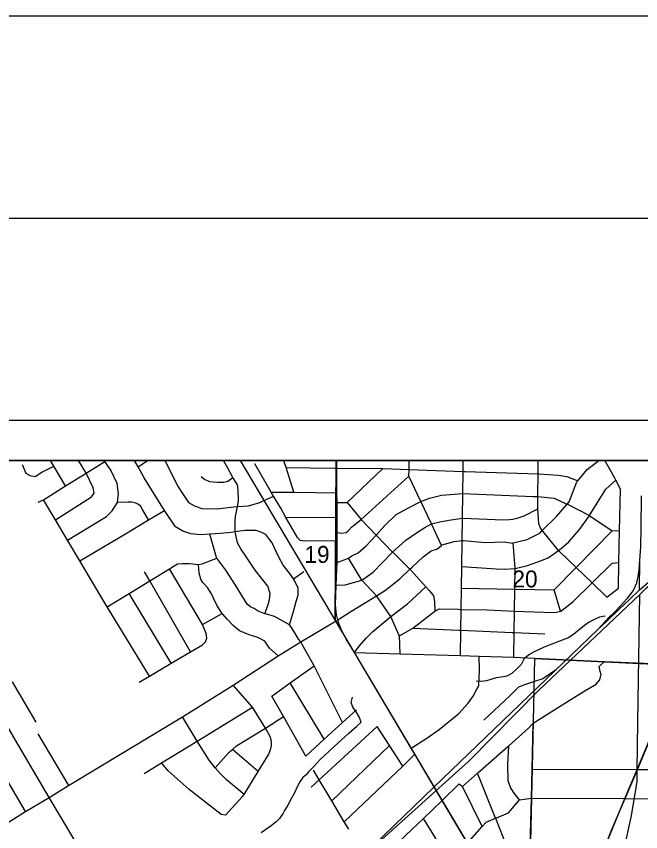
# Model space of a CAD drawing. Extents: x 0 to 34, y 0 to 22.
# Drawn here: x 2.713 to 4.259, y 19.981 to 22 of the extents above; entities that cross this region are included whole.
import ezdxf

# ---------------------------------------------------------------- set-up
doc = ezdxf.new("R2010")
doc.units = 0
for name, color, linetype in [('GM_X_City_Street', 7, 'Continuous'), ('GM_X_Corporation', 7, 'Continuous'), ('GM_X_County_Road', 7, 'Continuous'), ('GM_X_Minor_River', 7, 'Continuous'), ('GM_X_Rail_Line', 7, 'Continuous'), ('GM_X_Section_Text', 7, 'Continuous'), ('GM_X_US_Route', 7, 'Continuous'), ('SH_Border', 7, 'Continuous'), ('SH_Cut_Line', 7, 'Continuous'), ('SH_Data', 7, 'Continuous')]:
    doc.layers.add(name, color=color, linetype=linetype)

msp = doc.modelspace()

# ---------------------------------------------------------------- linework, layer by layer
at = {"layer": 'GM_X_City_Street'}
for p, q in [((3.0145, 20.8851), (3.038, 20.9)), ((3.3813, 20.8827), (3.5007, 20.8815)), ((3.3805, 20.7591), (3.507, 20.76)), ((3.1734, 20.4944), (3.0917, 20.6326)), ((3.399, 20.6076), (3.425, 20.6254)), ((3.0966, 20.3986), (2.992, 20.5711)), ((4.0605, 20.5275), (4.0442, 20.58)), ((3.4751, 20.2102), (3.3905, 20.3499)), ((2.7661, 20.2234), (2.8424, 20.0955)), ((3.3118, 20.1307), (3.2482, 20.1853)), ((3.4939, 20.0578), (3.6368, 20.195)), ((3.8666, 19.994), (3.8175, 20.0936)), ((3.2306, 20.0226), (3.2721, 20.0681)), ((3.8127, 19.8665), (3.7208, 20.0144))]:
    msp.add_line(p, q, dxfattribs=at)
for points in [[(3.2328, 19.5422), (3.103, 19.591), (3.1, 19.5922), (3.0838, 19.5999), (3.0684, 19.6092), (3.0409, 19.6497), (3.0185, 19.6872), (2.9804, 19.7509), (2.9484, 19.8044), (2.9186, 19.8559), (2.8857, 19.9126), (2.7945, 20.0661), (2.7105, 20.2083), (2.6457, 20.3192), (2.6128, 20.3748), (2.5459, 20.4886), (2.4669, 20.6187), (2.457, 20.6368), (2.3011, 20.9)], [(2.767, 20.7969), (2.7802, 20.8033), (2.8346, 20.8373), (2.8857, 20.8692), (2.9322, 20.8983)], [(2.8346, 20.8373), (2.8056, 20.886), (2.7972, 20.9)], [(2.8097, 20.7537), (2.8989, 20.8102), (2.9057, 20.8197), (2.9031, 20.8326), (2.8857, 20.8692), (2.8849, 20.871), (2.8671, 20.9)], [(2.8399, 20.703), (2.9174, 20.7501), (2.9363, 20.7618), (2.95, 20.7757), (2.963, 20.7962), (2.9632, 20.7976), (2.9658, 20.8178), (2.9629, 20.8436), (2.9472, 20.8767), (2.9322, 20.8983), (2.931, 20.9)], [(3.389, 20.4938), (3.3995, 20.5265), (3.4057, 20.5511), (3.4103, 20.5666), (3.4104, 20.5841), (3.4018, 20.6035), (3.399, 20.6076), (3.3895, 20.6214), (3.3737, 20.6409), (3.3625, 20.6607), (3.3539, 20.6801), (3.3461, 20.6964), (3.3382, 20.7071), (3.3304, 20.717), (3.3206, 20.7224), (3.3063, 20.727), (3.2783, 20.7272), (3.2548, 20.7239), (3.2443, 20.7224), (3.2186, 20.7199), (3.1921, 20.7179), (3.1914, 20.7178), (3.1687, 20.716), (3.1449, 20.7185), (3.125, 20.7254), (3.1069, 20.7365), (3.0799, 20.7765), (3.0294, 20.8577), (3.0145, 20.8851), (3.0054, 20.9)], [(3.0806, 20.9), (3.0967, 20.8679), (3.112, 20.8378), (3.1263, 20.8161), (3.1394, 20.7963), (3.1537, 20.7882), (3.1721, 20.7817), (3.2095, 20.7807), (3.2586, 20.7861), (3.2603, 20.7862), (3.2881, 20.7882), (3.3161, 20.7964), (3.3225, 20.7994), (3.3499, 20.8121)], [(3.3283, 20.5212), (3.3361, 20.5439), (3.3396, 20.5564), (3.3412, 20.5712), (3.3356, 20.5891), (3.3042, 20.6291), (3.2824, 20.6611), (3.2686, 20.6813), (3.2604, 20.6962), (3.2548, 20.7239), (3.2547, 20.7505), (3.2559, 20.7618), (3.2603, 20.7862), (3.2629, 20.8009), (3.2619, 20.8275), (3.2605, 20.84), (3.249, 20.8579), (3.2362, 20.8811), (3.2265, 20.8987), (3.2261, 20.9)], [(3.4001, 20.8217), (3.3813, 20.8827), (3.376, 20.897), (3.3754, 20.9)], [(3.7657, 20.6898), (3.7405, 20.7432), (3.7143, 20.7991), (3.6848, 20.8615), (3.6851, 20.878), (3.6853, 20.9)], [(3.8127, 20.4176), (3.8136, 20.48), (3.8143, 20.5319), (3.8151, 20.5847), (3.8159, 20.6381), (3.8168, 20.702), (3.8176, 20.7579), (3.8185, 20.8187), (3.8193, 20.8734), (3.8196, 20.9)], [(4.1752, 20.5621), (4.1384, 20.5976), (4.099, 20.6354), (4.0567, 20.6761), (4.0554, 20.6776), (4.0161, 20.7251), (4.0149, 20.7269), (4.0103, 20.734), (4.0067, 20.7439), (4.0042, 20.7808), (4.0041, 20.7823), (4.0044, 20.8111), (4.0044, 20.8145), (4.005, 20.867), (4.0052, 20.8885), (4.0052, 20.9)], [(4.1752, 20.5621), (4.2037, 20.5847), (4.2049, 20.648), (4.2065, 20.7273), (4.2085, 20.8298), (4.1969, 20.852), (4.1944, 20.8567), (4.1827, 20.8792), (4.1696, 20.9)], [(2.7274, 20.8905), (2.7366, 20.869), (2.7416, 20.8662), (2.7466, 20.8634), (2.7598, 20.8611), (2.7756, 20.8712), (2.8056, 20.886)], [(3.5071, 20.7012), (3.427, 20.7009), (3.4156, 20.7021), (3.4089, 20.7094), (3.3805, 20.7591), (3.3674, 20.7821), (3.3499, 20.8121), (3.3439, 20.8223), (3.3035, 20.8918)], [(3.5007, 20.8815), (3.5067, 20.8814), (3.6201, 20.8803), (3.6851, 20.878), (3.8193, 20.8734), (3.824, 20.8733), (4.005, 20.867), (4.0065, 20.867), (4.0544, 20.8641), (4.0706, 20.8616), (4.0755, 20.8607), (4.1027, 20.8499)], [(3.5069, 20.7968), (3.5324, 20.7962), (3.6201, 20.8803)], [(3.1703, 20.861), (3.1794, 20.8534), (3.1881, 20.8499), (3.191, 20.8488), (3.2107, 20.8467), (3.2269, 20.847), (3.2364, 20.8489), (3.249, 20.8579)], [(3.5071, 20.7221), (3.5192, 20.7201), (3.5294, 20.7219), (3.5355, 20.7272), (3.5434, 20.7361), (3.5669, 20.7546), (3.6848, 20.8615)], [(3.8159, 20.6381), (3.9007, 20.6324), (3.921, 20.631), (3.9483, 20.6329), (3.9782, 20.6405), (4.0105, 20.6522), (4.0299, 20.6595), (4.0554, 20.6776), (4.0566, 20.6785), (4.0807, 20.699), (4.1073, 20.7298), (4.1312, 20.7628), (4.1319, 20.7641), (4.1559, 20.8031), (4.1722, 20.8298), (4.1969, 20.852)], [(3.3439, 20.8223), (3.4001, 20.8217), (3.5068, 20.8204)], [(3.5072, 20.6481), (3.5354, 20.6582), (3.5434, 20.6641), (3.5595, 20.6714), (3.5787, 20.6888), (3.6041, 20.7158), (3.6252, 20.7395), (3.6537, 20.7666), (3.6858, 20.7842), (3.7126, 20.7984), (3.7143, 20.7991), (3.7358, 20.8071), (3.7655, 20.8148), (3.8185, 20.8187), (3.9925, 20.8116), (4.0044, 20.8111), (4.0443, 20.8073), (4.0713, 20.795), (4.0767, 20.7922), (4.0774, 20.7919), (4.1319, 20.7641), (4.1326, 20.7637), (4.1885, 20.7262), (4.2065, 20.7273)], [(3.0422, 20.3664), (2.9381, 20.5378), (2.9233, 20.5627), (2.87, 20.6522), (2.8399, 20.703), (2.8097, 20.7537), (2.7802, 20.8033)], [(3.0403, 20.7531), (3.0253, 20.779), (3.0202, 20.7878), (3.0141, 20.7919), (3.0087, 20.7949), (2.9992, 20.797), (2.9894, 20.797), (2.9789, 20.7966), (2.9632, 20.7976)], [(3.5324, 20.7962), (3.5669, 20.7546), (3.6041, 20.7158), (3.6445, 20.6737), (3.645, 20.6731), (3.687, 20.6313), (3.6879, 20.6304), (3.6893, 20.6289), (3.7266, 20.5878), (3.7344, 20.5793), (3.7396, 20.5728), (3.7459, 20.5651), (3.7479, 20.5514), (3.7492, 20.5275)], [(2.87, 20.6522), (2.983, 20.7191), (3.0403, 20.7531), (3.0799, 20.7765)], [(3.5044, 20.5919), (3.5269, 20.5928), (3.5683, 20.6044), (3.5967, 20.6241), (3.619, 20.6473), (3.6445, 20.6737), (3.6776, 20.7034), (3.7036, 20.7209), (3.7242, 20.7346), (3.7405, 20.7432), (3.7618, 20.7482), (3.7838, 20.7528), (3.8176, 20.7579), (3.919, 20.7532), (3.9342, 20.7545), (3.9425, 20.7552), (3.9531, 20.7573), (3.9702, 20.7635), (4.0042, 20.7808)], [(3.3928, 20.4892), (3.389, 20.4938), (3.3517, 20.5143), (3.3294, 20.5208), (3.3283, 20.5212), (3.3113, 20.5276), (3.3014, 20.5337), (3.2931, 20.5375), (3.2844, 20.5451), (3.2554, 20.5921), (3.2316, 20.6289), (3.2095, 20.6583), (3.2082, 20.66), (3.1921, 20.7179)], [(3.8151, 20.5847), (3.9474, 20.582), (4.0442, 20.58), (4.099, 20.6354), (4.1885, 20.7262)], [(3.9444, 20.4137), (3.9455, 20.4746), (3.9464, 20.5278), (3.9474, 20.582), (3.9483, 20.6329), (3.9483, 20.6337), (3.9432, 20.6963)], [(2.9381, 20.5378), (2.992, 20.5711), (3.0432, 20.6027), (3.0917, 20.6326), (3.1036, 20.6399), (3.1115, 20.6448), (3.1247, 20.6452), (3.1425, 20.6456), (3.1636, 20.6429), (3.1727, 20.6445), (3.1836, 20.6483), (3.1916, 20.6517), (3.2095, 20.6583)], [(3.6635, 20.422), (3.6618, 20.4666), (3.6601, 20.469), (3.6403, 20.5141), (3.6045, 20.5654), (3.5683, 20.6044), (3.5354, 20.6582)], [(3.3613, 20.4171), (3.3395, 20.4362), (3.3282, 20.4532), (3.3112, 20.4623), (3.2897, 20.4688), (3.2652, 20.4787), (3.25, 20.4923), (3.2349, 20.5075), (3.224, 20.5196), (3.2229, 20.5213), (3.2104, 20.5405), (3.2014, 20.5595), (3.1964, 20.5701), (3.1863, 20.586), (3.1749, 20.5982), (3.1693, 20.6065), (3.1659, 20.6217), (3.1636, 20.6429)], [(3.6943, 20.4849), (3.7492, 20.5275), (3.7595, 20.533), (3.8072, 20.532), (3.8143, 20.5319), (3.8786, 20.5306), (3.9464, 20.5278), (4.0425, 20.5238), (4.0505, 20.5248), (4.0605, 20.5275), (4.0611, 20.5276), (4.0907, 20.5509), (4.1384, 20.5976), (4.1884, 20.6465), (4.2049, 20.648)], [(3.1445, 20.4271), (3.0432, 20.6027), (3.0303, 20.625)], [(3.55, 20.4254), (3.5616, 20.4406), (3.5802, 20.4613), (3.5956, 20.4767), (3.6403, 20.5141), (3.6817, 20.5459), (3.7266, 20.5878)], [(3.0169, 20.3514), (3.0422, 20.3664), (3.0966, 20.3986), (3.1445, 20.4271), (3.1735, 20.4443), (3.1811, 20.4518), (3.1849, 20.4605), (3.1827, 20.4719), (3.1734, 20.4944), (3.2229, 20.5213)], [(3.4208, 20.4452), (3.4173, 20.4515), (3.4118, 20.4578), (3.4023, 20.4734), (3.3928, 20.4892)], [(3.6618, 20.4666), (3.6943, 20.4849), (3.8088, 20.4802), (3.8136, 20.48), (3.9406, 20.4748), (3.9455, 20.4746), (4.0217, 20.4715)], [(3.5204, 20.2515), (3.4504, 20.392), (3.4208, 20.4452)], [(3.6904, 20.1886), (3.7294, 20.2129), (3.76, 20.2343), (3.8087, 20.274), (3.8313, 20.2996), (3.8438, 20.3171), (3.8525, 20.3325), (3.8577, 20.3426), (3.8598, 20.382), (3.8588, 20.4162)], [(3.3455, 20.317), (3.3905, 20.3499), (3.4504, 20.392)], [(3.7675, 20.0588), (3.8093, 20.0998), (3.8175, 20.0936), (3.8551, 20.1264), (3.931, 20.1929), (3.9321, 20.1939), (3.9812, 20.2376), (3.9913, 20.2491), (3.9928, 20.25), (4.0688, 20.2976), (4.1233, 20.3316), (4.1486, 20.3469), (4.1575, 20.3577), (4.1605, 20.3717), (4.158, 20.3782), (4.1561, 20.3904), (4.1692, 20.4031)], [(2.7029, 20.3524), (2.761, 20.2526)], [(3.3445, 20.2018), (3.3435, 20.209), (3.3415, 20.2169), (3.3294, 20.2376), (3.298, 20.2896), (3.2494, 20.3446)], [(3.4297, 20.1687), (3.374, 20.2668), (3.3455, 20.317)], [(3.0293, 20.1257), (3.0727, 20.1523), (3.1606, 20.2059), (3.298, 20.2896)], [(3.205, 20.1396), (3.2396, 20.1783), (3.2482, 20.1853), (3.2581, 20.194), (3.2754, 20.2049), (3.3294, 20.2376), (3.374, 20.2668)], [(3.4297, 20.1687), (3.4751, 20.2102), (3.5204, 20.2515), (3.5548, 20.2829)], [(3.2769, 20.0734), (3.2333, 20.1102), (3.2179, 20.1256), (3.205, 20.1396), (3.1905, 20.1582), (3.1606, 20.2059), (3.1241, 20.266)], [(3.982, 19.7998), (3.984, 19.8823), (3.9862, 19.9743), (3.9883, 20.0642), (3.9901, 20.1362), (3.9928, 20.25)], [(3.4429, 20.0916), (3.4628, 20.11), (3.6063, 20.2422)], [(3.6697, 20.144), (3.6368, 20.195), (3.6063, 20.2422)], [(2.7356, 20.0311), (2.6514, 20.1741), (2.6283, 20.2138)], [(3.2721, 20.0681), (3.2769, 20.0734), (3.3118, 20.1307), (3.3377, 20.1736), (3.3408, 20.1797), (3.3433, 20.1873), (3.3446, 20.1947), (3.3445, 20.2018)], [(3.959, 20.0602), (3.9458, 20.0768), (3.9395, 20.0857), (3.9367, 20.0906), (3.9362, 20.0914), (3.9305, 20.1075), (3.9299, 20.1481), (3.9321, 20.1939)], [(3.5247, 20.0062), (3.6697, 20.144), (3.6996, 20.1731)], [(3.2306, 20.0226), (3.2197, 20.0244), (3.1411, 20.0859), (3.0886, 20.1318), (3.0727, 20.1523)], [(3.5358, 19.9877), (3.5247, 20.0062), (3.4939, 20.0578), (3.4628, 20.11), (3.4486, 20.1337)], [(3.9522, 19.8826), (3.9182, 19.9679), (3.8999, 20.0139), (3.8995, 20.0149), (3.8551, 20.1264)], [(3.9901, 20.1362), (4.2497, 20.1354), (4.2594, 20.1353), (4.2827, 20.1353), (4.416, 20.1371), (4.483, 20.1379), (4.4857, 20.138), (4.5071, 20.1315), (4.5345, 20.1176), (4.5425, 20.1136), (4.5602, 20.1046)], [(3.5679, 19.8689), (3.5929, 19.8927), (3.6364, 19.9341), (3.6774, 19.973), (3.7208, 20.0144), (3.7675, 20.0588)], [(3.8303, 19.9528), (3.8666, 19.994), (3.8762, 20.005), (3.8995, 20.0149), (3.914, 20.0211), (3.9315, 20.0285), (3.959, 20.0602), (3.9883, 20.0642), (4.2198, 20.0634), (4.282, 20.0632), (4.4149, 20.0627), (4.5047, 20.0624)]]:
    msp.add_lwpolyline(points, dxfattribs=at)
at = {"layer": 'GM_X_Corporation'}
msp.add_lwpolyline([(5.8906, 20.9), (2.1, 20.9)], dxfattribs=at)
msp.add_lwpolyline([(5.8906, 20.9), (2.1, 20.9)], dxfattribs=at)
msp.add_lwpolyline([(5.8906, 20.9), (2.1, 20.9)], dxfattribs=at)
for points in [[(3.5047, 20.9), (3.2673, 20.9), (3.5021, 20.5045)], [(4.5069, 20.9), (3.5047, 20.9), (3.5021, 20.5045), (3.8703, 19.8849), (3.9848, 19.8833), (3.9912, 20.1387), (3.9967, 20.4103), (4.4998, 20.3861), (4.5031, 20.6381)]]:
    msp.add_lwpolyline(points, close=True, dxfattribs=at)
at = {"layer": 'GM_X_County_Road'}
for points in [[(3.5091, 20.5061), (3.5058, 20.5195), (3.5032, 20.542), (3.5044, 20.5919), (3.5072, 20.6481), (3.5071, 20.7012), (3.5071, 20.7221), (3.507, 20.76), (3.5069, 20.7968), (3.5068, 20.8204), (3.5067, 20.8814), (3.5066, 20.9)], [(3.5091, 20.5061), (3.5407, 20.5264), (3.6045, 20.5654), (3.6267, 20.5797), (3.6625, 20.6077), (3.687, 20.6313), (3.6926, 20.6366), (3.7205, 20.6618), (3.7403, 20.6764), (3.7554, 20.6816), (3.7657, 20.6898), (3.7676, 20.6914), (3.7972, 20.7002), (3.8168, 20.702), (3.8203, 20.7023), (3.8739, 20.6977), (3.9208, 20.6988), (3.9415, 20.696), (3.9432, 20.6963), (3.9779, 20.7044), (4.0087, 20.7208), (4.0149, 20.7269), (4.0499, 20.7614), (4.0767, 20.7922), (4.0816, 20.7979), (4.1007, 20.8475), (4.1027, 20.8499), (4.1263, 20.878), (4.1552, 20.9)], [(2.5595, 19.947), (2.579, 19.9473), (2.6022, 19.953), (2.6279, 19.9637), (2.6781, 19.9948), (2.7356, 20.0311), (2.7945, 20.0661), (2.8424, 20.0955), (3.1241, 20.266), (3.2494, 20.3446), (3.3613, 20.4171), (3.4173, 20.4515), (3.5091, 20.5061)], [(4.0431, 19.6205), (4.042, 19.6235), (4.0403, 19.6258), (4.0359, 19.6277), (4.0329, 19.6283), (4.0301, 19.6303), (4.0261, 19.6334), (4.0182, 19.639), (3.9202, 19.8013), (3.9093, 19.8197), (3.8716, 19.8831), (3.8633, 19.8972), (3.8303, 19.9528), (3.7675, 20.0588), (3.6996, 20.1731), (3.6904, 20.1886), (3.55, 20.4254), (3.5307, 20.4572), (3.5187, 20.4784), (3.5116, 20.4967), (3.5091, 20.5061)], [(3.55, 20.4254), (3.6635, 20.422), (3.8127, 20.4176), (3.8588, 20.4162), (3.9444, 20.4137), (4.1692, 20.4031), (4.2873, 20.3976), (4.3579, 20.3943)]]:
    msp.add_lwpolyline(points, dxfattribs=at)
at = {"layer": 'GM_X_Minor_River'}
for points in [[(4.1706, 20.5152), (4.1566, 20.5126), (4.1445, 20.507), (4.1312, 20.4999), (4.1195, 20.4916), (4.1062, 20.4811), (4.0932, 20.4702), (4.0799, 20.4616), (4.058, 20.4534), (4.0451, 20.4485), (4.0318, 20.443), (4.0197, 20.4381), (4.0076, 20.4329), (3.9947, 20.4265), (3.9818, 20.4194), (3.9696, 20.4085), (3.9627, 20.3956), (3.952, 20.3847), (3.9398, 20.3734), (3.9277, 20.3667), (3.9141, 20.3638), (3.9008, 20.362), (3.8876, 20.3583), (3.877, 20.3549), (3.8634, 20.3535), (3.8513, 20.354)], [(3.536, 20.2252), (3.5558, 20.2427), (3.5668, 20.2528), (3.562, 20.2658), (3.5545, 20.278), (3.5463, 20.2898), (3.5422, 20.3012), (3.545, 20.3141)], [(3.536, 20.2252), (3.4992, 20.1912), (3.4654, 20.1598), (3.4501, 20.1434), (3.4374, 20.1303), (3.4301, 20.1224), (3.4224, 20.1157), (3.4147, 20.1052), (3.4089, 20.0943), (3.4014, 20.078), (3.3944, 20.0645), (3.3851, 20.0472), (3.3769, 20.0336), (3.3723, 20.0257), (3.3692, 20.0212), (3.3649, 20.0148), (3.3565, 20.0062), (3.3438, 19.9962), (3.3194, 19.9783)]]:
    msp.add_lwpolyline(points, dxfattribs=at)
at = {"layer": 'GM_X_Rail_Line'}
msp.add_line((4.2554, 20.5789), (4.2567, 20.6536), dxfattribs=at)
for points in [[(2.1, 18.5112), (2.2808, 18.6845), (2.4535, 18.8489), (2.9301, 19.3073), (3.2236, 19.5884), (3.5987, 19.9488), (3.7467, 20.0915), (4.153, 20.482), (4.1749, 20.5028), (4.2055, 20.5325), (4.23, 20.5556), (4.2554, 20.5802), (4.2776, 20.5982), (4.4577, 20.7589), (4.5352, 20.8259), (4.6176, 20.9)], [(4.153, 20.482), (4.1711, 20.5021), (4.1814, 20.513), (4.1957, 20.5267), (4.2079, 20.5397), (4.2161, 20.5492), (4.226, 20.5596), (4.2328, 20.5675), (4.2383, 20.5755), (4.2424, 20.5825), (4.2462, 20.5904), (4.249, 20.5978), (4.251, 20.6057), (4.2523, 20.6122), (4.2537, 20.6198), (4.2548, 20.6294), (4.2558, 20.6431), (4.2587, 20.6868), (4.2602, 20.7337), (4.2608, 20.8128)], [(4.2498, 20.1328), (4.3597, 20.3971), (4.5065, 20.7546)], [(4.2565, 20.5683), (4.2734, 20.5854), (4.3256, 20.6312), (4.3739, 20.663), (4.4971, 20.7486), (4.5065, 20.7546)], [(2.1, 18.4964), (2.427, 18.8067), (2.94, 19.2985), (3.6093, 19.9545), (3.8333, 20.1564), (4.0064, 20.3322), (4.2565, 20.5683)], [(4.2498, 20.1328), (4.252, 20.2533), (4.2565, 20.5683)], [(4.0499, 20.3829), (4.0165, 20.3601), (3.9957, 20.3532), (3.9711, 20.3453), (3.9563, 20.3389), (3.9357, 20.3188), (3.8703, 20.2574)], [(2.4678, 18.203), (2.4782, 18.2477), (2.488, 18.3737), (2.5357, 18.4142), (2.9805, 18.6646), (3.2242, 18.8065), (3.5197, 18.9635), (3.5859, 19.0057), (3.6341, 19.0441), (3.8802, 19.2692), (3.9999, 19.5199), (4.1873, 19.9868), (4.2498, 20.1328)], [(4.1888, 19.2485), (4.1218, 19.3219), (4.0932, 19.3761), (4.0721, 19.4386), (4.0676, 19.4913), (4.0721, 19.5546), (4.0887, 19.6133), (4.2166, 19.9348), (4.2362, 20.0206), (4.2498, 20.1057), (4.2498, 20.1328)]]:
    msp.add_lwpolyline(points, dxfattribs=at)
at = {"layer": 'GM_X_US_Route'}
msp.add_lwpolyline([(4.0592, 19.6756), (4.0604, 19.6793), (4.0888, 19.7484), (4.1089, 19.7968), (4.144, 19.8811), (4.1805, 19.9691), (4.2198, 20.0634), (4.2497, 20.1354), (4.2513, 20.1393), (4.281, 20.2104), (4.3085, 20.276), (4.3396, 20.3506), (4.3579, 20.3943), (4.3666, 20.4151), (4.3869, 20.4638), (4.4008, 20.4969), (4.4073, 20.513), (4.4334, 20.577), (4.4582, 20.6377), (4.4942, 20.726), (4.4965, 20.7318), (4.4969, 20.7327)], dxfattribs=at)
at = {"layer": 'SH_Border'}
msp.add_lwpolyline([(1.5, 21.5), (33.5, 21.5), (33.5, 0.5), (1.5, 0.5)], close=True, dxfattribs=at)
at = {"layer": 'SH_Cut_Line'}
msp.add_lwpolyline([(0, 0), (34, 0), (34, 22), (0, 22)], close=True, dxfattribs=at)
at = {"layer": 'SH_Data'}
for p, q in [((2, 21), (9, 21)), ((2, 21), (9, 21)), ((2.1, 20.9), (8.9, 20.9)), ((2.1, 20.9), (8.9, 20.9))]:
    msp.add_line(p, q, dxfattribs=at)

# ---------------------------------------------------------------- texts
at = {"layer": 'GM_X_Section_Text'}
for s, p in [('19', (3.4262, 20.647)), ('20', (3.9412, 20.5862))]:
    msp.add_text(s, height=0.04186, rotation=0, dxfattribs=at).set_placement(p)

doc.saveas('drawing.dxf')
